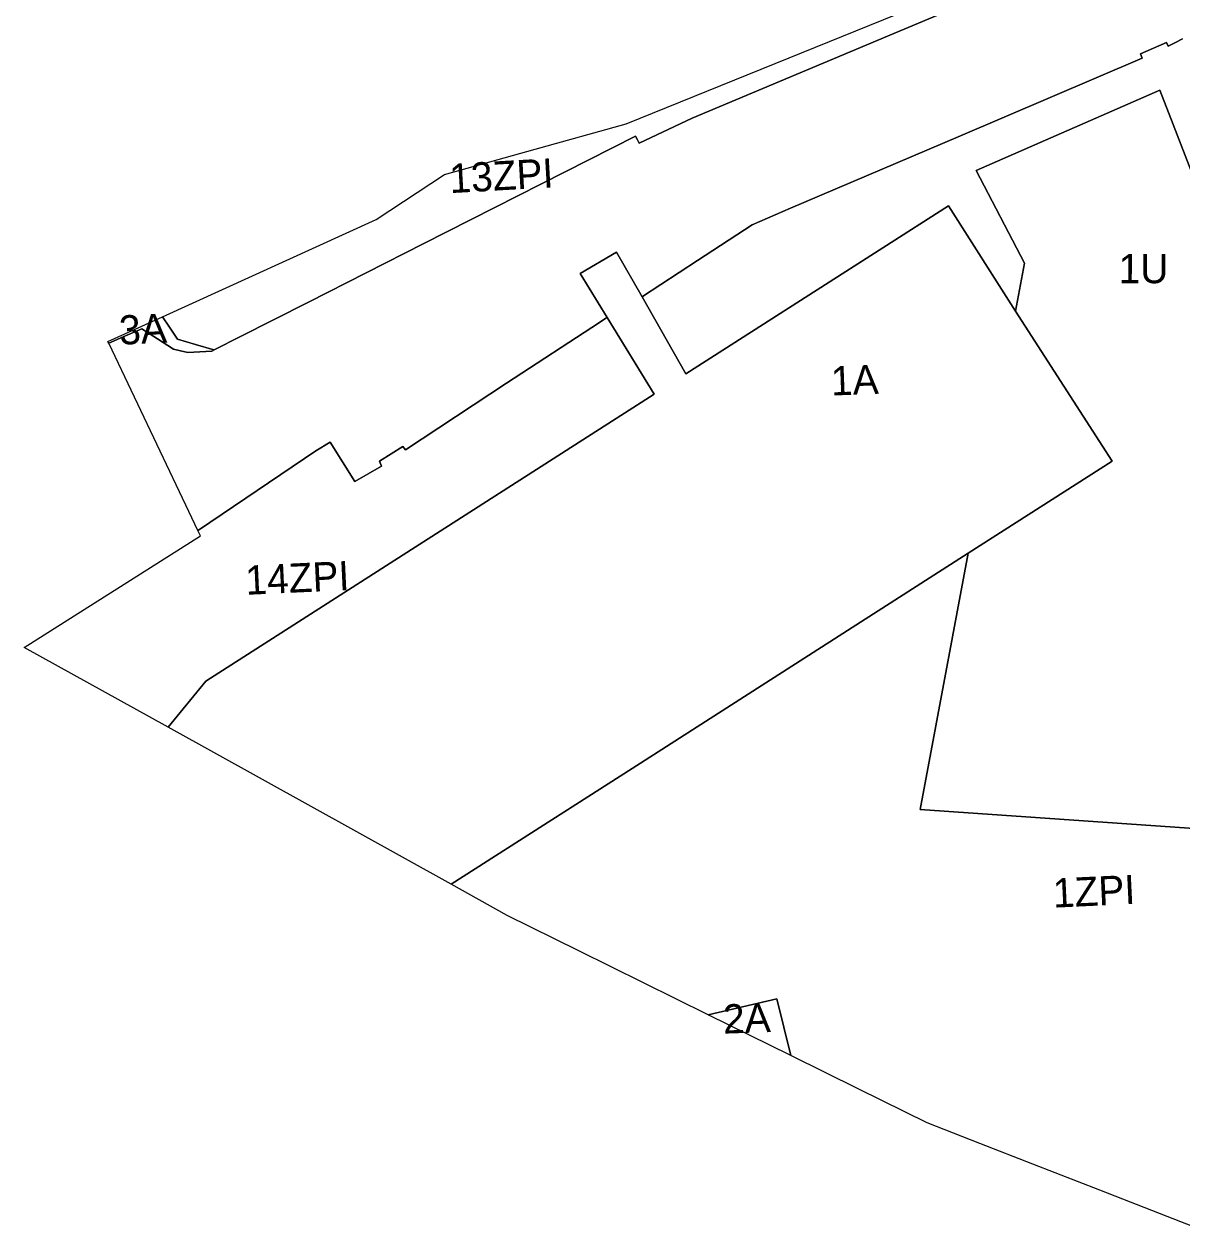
# Model space of a CAD drawing. Extents: x 7418021 to 7419743, y 5540231 to 5541685.
# Drawn here: x 7418020.6 to 7418417.6, y 5540536.2 to 5540950.4 of the extents above; entities that cross this region are included whole.
import ezdxf

# ---------------------------------------------------------------- set-up
doc = ezdxf.new("R2010")
doc.units = 0
doc.layers.add('linie_rozgraniczajace', color=7, linetype='Continuous')
doc.layers.add('oznaczenia_przeznaczen', color=7, linetype='Continuous')

msp = doc.modelspace()

# ---------------------------------------------------------------- linework, layer by layer
at = {"layer": 'linie_rozgraniczajace'}
for points in [[(7418393.97, 5540983.68), (7418392.2, 5540981.51), (7418387.85, 5540976.17), (7418318.78, 5540947.18), (7418249.71, 5540918.18), (7418231.54, 5540909.52), (7418230.9, 5540910.77), (7418230.26, 5540912.02), (7418157.63, 5540875.13), (7418118.14, 5540855.08), (7418094.31, 5540842.98), (7418086.26, 5540838.9), (7418085.93, 5540838.77), (7418085.59, 5540838.64), (7418079.4, 5540840.52), (7418073.21, 5540842.4), (7418070.21, 5540846.77), (7418067.99, 5540850.01), (7418141.34, 5540883.41), (7418164.76, 5540898.82), (7418195.88, 5540907.53), (7418227, 5540916.23), (7418324.43, 5540955.59), (7418389.45, 5540981.85)], [(7418232.47, 5540856.89), (7418247.54, 5540830.44), (7418337.55, 5540888.08), (7418360.55, 5540851.98), (7418393.64, 5540800.48), (7418344.34, 5540768.9), (7418229.07, 5540695.1), (7418167.01, 5540655.36), (7418069.94, 5540709.22), (7418082.89, 5540725.01), (7418236.67, 5540823.47), (7418220.52, 5540849.82), (7418211.28, 5540864.89), (7418223.75, 5540872.19)], [(7418220.52, 5540849.82), (7418236.67, 5540823.47), (7418082.89, 5540725.01), (7418069.94, 5540709.22), (7418020.59, 5540736.6), (7418081.01, 5540774.88), (7418080.13, 5540776.72), (7418080.33, 5540776.85), (7418120.62, 5540804), (7418125.57, 5540806.98), (7418134.03, 5540793.5), (7418143.14, 5540798.78), (7418142.46, 5540800.5), (7418150.45, 5540805.53), (7418151.31, 5540804.44), (7418186.03, 5540827.21), (7418217.89, 5540848.1), (7418220.42, 5540849.76)], [(7418067.99, 5540850.01), (7418070.21, 5540846.77), (7418073.21, 5540842.4), (7418079.4, 5540840.52), (7418085.59, 5540838.64), (7418085.93, 5540838.77), (7418084.99, 5540838.25), (7418080.85, 5540838.01), (7418076.71, 5540837.78), (7418074.25, 5540838.36), (7418071.78, 5540838.95), (7418066.36, 5540842.44), (7418060.93, 5540845.93), (7418054.57, 5540843.12), (7418049.6, 5540840.93), (7418049.33, 5540841.52)], [(7418255.17, 5540610.65), (7418278.73, 5540616.07), (7418283.45, 5540596.69)]]:
    msp.add_lwpolyline(points, close=True, dxfattribs=at)
for points in [[(7418080.13, 5540776.72), (7418076.02, 5540785.37), (7418049.6, 5540840.93), (7418054.57, 5540843.12), (7418060.93, 5540845.93), (7418066.36, 5540842.44), (7418071.78, 5540838.95), (7418074.25, 5540838.36), (7418076.71, 5540837.78), (7418080.85, 5540838.01), (7418084.99, 5540838.25), (7418085.93, 5540838.77), (7418086.26, 5540838.9), (7418094.31, 5540842.98), (7418118.14, 5540855.08), (7418157.63, 5540875.13), (7418230.26, 5540912.02), (7418230.9, 5540910.77), (7418231.54, 5540909.52), (7418249.71, 5540918.18), (7418318.78, 5540947.18), (7418387.85, 5540976.17)], [(7418417.81, 5540945.3), (7418415.38, 5540944.05), (7418412.95, 5540942.8), (7418412.38, 5540944.05), (7418407.88, 5540942.13), (7418403.37, 5540940.21), (7418404.04, 5540938.75), (7418340.91, 5540911.75), (7418283.44, 5540887.24), (7418270.23, 5540881.59), (7418251.44, 5540869.3), (7418232.66, 5540857.01), (7418232.47, 5540856.89), (7418223.75, 5540872.19), (7418211.28, 5540864.89), (7418220.52, 5540849.82), (7418220.42, 5540849.76), (7418217.89, 5540848.1), (7418186.03, 5540827.21), (7418151.31, 5540804.44), (7418150.45, 5540805.53), (7418142.46, 5540800.5), (7418143.14, 5540798.78), (7418134.03, 5540793.5), (7418125.57, 5540806.98), (7418120.62, 5540804), (7418080.33, 5540776.85), (7418080.13, 5540776.72)], [(7418428.31, 5540880.55), (7418414.61, 5540915.96), (7418410.07, 5540927.71), (7418347.05, 5540900.25), (7418363.62, 5540868.41), (7418360.55, 5540851.98), (7418337.55, 5540888.08), (7418247.54, 5540830.44), (7418232.47, 5540856.89), (7418232.66, 5540857.01), (7418251.44, 5540869.3), (7418270.23, 5540881.59), (7418283.44, 5540887.24), (7418340.91, 5540911.75), (7418404.04, 5540938.75), (7418403.37, 5540940.21), (7418407.88, 5540942.13), (7418412.38, 5540944.05), (7418412.95, 5540942.8), (7418415.38, 5540944.05), (7418417.81, 5540945.3)], [(7418423.36, 5540674.41), (7418375.61, 5540677.74), (7418327.87, 5540681.07), (7418344.34, 5540768.9), (7418393.64, 5540800.48), (7418360.55, 5540851.98), (7418363.62, 5540868.41), (7418347.05, 5540900.25), (7418410.07, 5540927.71), (7418414.61, 5540915.96), (7418428.31, 5540880.55)], [(7418426.01, 5540536.16), (7418412.56, 5540541.41), (7418389.51, 5540550.42), (7418366.46, 5540559.43), (7418348.37, 5540566.5), (7418330.28, 5540573.56), (7418306.87, 5540585.13), (7418283.45, 5540596.69), (7418278.73, 5540616.07), (7418255.17, 5540610.65), (7418232.97, 5540621.62), (7418210.76, 5540632.59), (7418186.2, 5540644.71), (7418167.01, 5540655.36), (7418229.07, 5540695.1), (7418344.34, 5540768.9), (7418327.87, 5540681.07), (7418375.61, 5540677.74), (7418423.36, 5540674.41)]]:
    msp.add_lwpolyline(points, dxfattribs=at)

# ---------------------------------------------------------------- texts
at = {"layer": 'oznaczenia_przeznaczen'}
for s, rotation, p in [('13ZPI', 3.2408, (7418166.68, 5540892.42)), ('1U', 359.9118, (7418395.89, 5540861.55)), ('3A', 2.7651, (7418053.37, 5540840.41)), ('1A', 2.1933, (7418297.42, 5540822.99)), ('14ZPI', 2.669, (7418096.66, 5540754.64)), ('1ZPI', 2.6921, (7418373.59, 5540647.34)), ('2A', 1.9516, (7418260.4, 5540604.13))]:
    msp.add_text(s, height=10, rotation=rotation, dxfattribs=at).set_placement(p)

doc.saveas('drawing.dxf')
